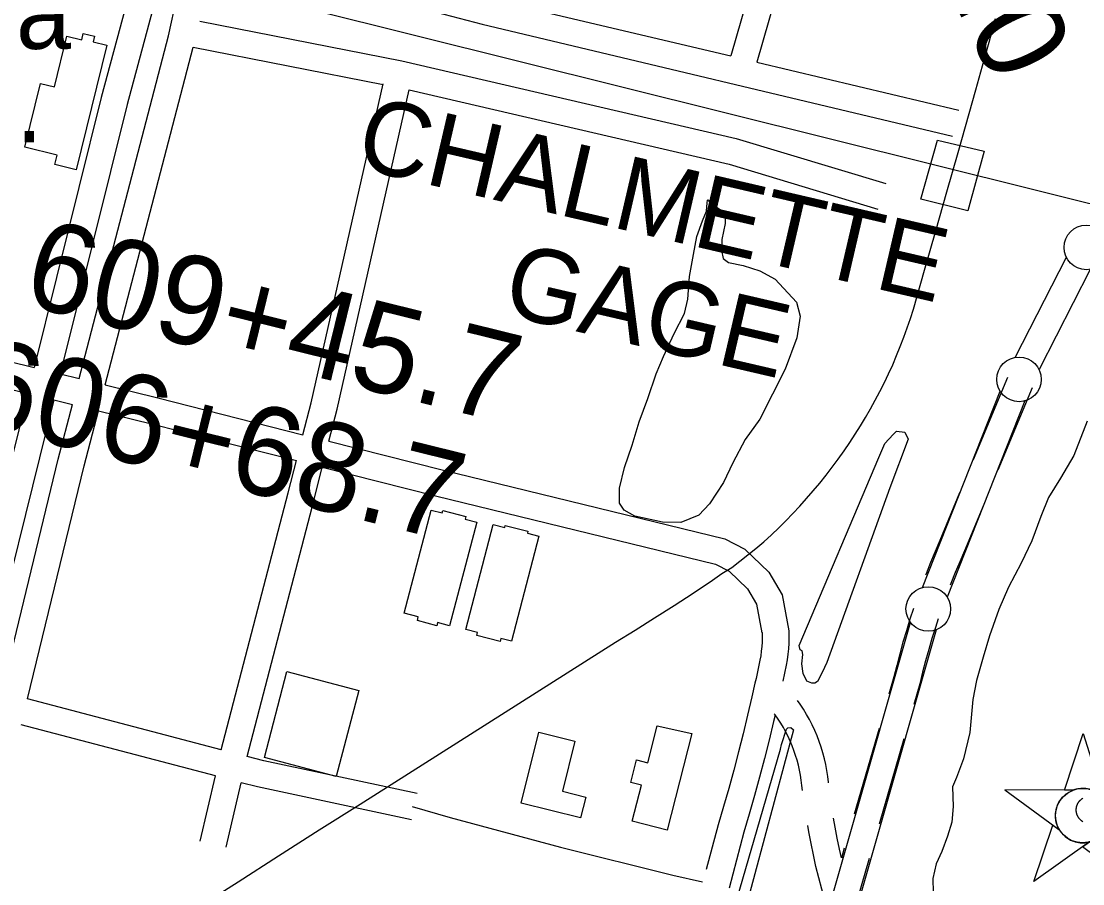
# Model space of a CAD drawing. Extents: x 3677843 to 3715951, y 511991 to 537744.
# Drawn here: x 3692882 to 3694073, y 534017 to 534986 of the extents above; entities that cross this region are included whole.
import ezdxf

# ---------------------------------------------------------------- set-up
doc = ezdxf.new("R2010")
doc.units = 0
for name, color, linetype in [('V-BLDG-IDEN', 7, 'Continuous'), ('V-BLDG-OTLN', 7, 'Continuous'), ('V-BRDG-OTLN', 7, 'Continuous'), ('V-CHAN-DOCK', 7, 'Continuous'), ('V-CHAN-NAID', 7, 'Continuous'), ('V-RAIL-TRAK', 7, 'Continuous'), ('V-RIVR-GAGE-IDEN', 7, 'Continuous'), ('V-ROAD-CNTR', 7, 'Continuous'), ('V-SITE-VEGE', 7, 'Continuous'), ('V-SURV-IDEN', 7, 'Continuous'), ('V-SURV-LINE', 7, 'Continuous'), ('V-TOPO-SHOR', 7, 'Continuous')]:
    doc.layers.add(name, color=color, linetype=linetype)

msp = doc.modelspace()

# ---------------------------------------------------------------- linework, layer by layer
at = {"layer": 'V-BLDG-OTLN'}
for points in [[(3692977.768, 534958.718), (3692943.644, 534818.9130000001), (3692919.6780000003, 534824.762), (3692922.24, 534835.256), (3692885.872, 534844.132), (3692903.348, 534915.714), (3692919.2630000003, 534911.831), (3692933.181, 534968.849), (3692949.806, 534964.79), (3692951.494, 534971.708), (3692963.977, 534968.659), (3692962.4590000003, 534962.453)], [(3693392.84, 534423.172), (3693362.3740000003, 534307.116), (3693349.009, 534310.6240000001), (3693348.0810000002, 534307.093), (3693326.278, 534312.816), (3693327.376, 534316.9940000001), (3693311.446, 534321.1730000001), (3693341.833, 534436.928), (3693354.252, 534433.6680000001), (3693355.022, 534436.599), (3693380.72, 534429.851), (3693379.862, 534426.58)], [(3693462.431, 534407.55), (3693431.9960000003, 534289.759), (3693419.9820000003, 534292.8640000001), (3693419.1380000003, 534289.591), (3693393.133, 534296.311), (3693393.934, 534299.416), (3693380.761, 534302.819), (3693411.186, 534420.571), (3693424.2630000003, 534417.194), (3693424.9220000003, 534419.742), (3693450.332, 534413.176), (3693449.725, 534410.833)], [(3693180.051, 534255.609), (3693260.711, 534234.387), (3693235.33, 534137.91), (3693154.67, 534159.134)], [(3693634.181, 534186.161), (3693606.481, 534077.66), (3693567.401, 534087.638), (3693577.754, 534128.1900000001), (3693565.775, 534131.246), (3693572.302, 534156.5650000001), (3693584.918, 534153.3420000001), (3693595.346, 534194.662)], [(3693503.1580000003, 534177.672), (3693489.051, 534121.393), (3693515.241, 534114.829), (3693509.345, 534091.312), (3693442.6410000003, 534108.032), (3693462.642, 534187.824)]]:
    msp.add_lwpolyline(points, close=True, dxfattribs=at)
at = {"layer": 'V-BRDG-OTLN'}
msp.add_lwpolyline([(3693891.272, 534786.02), (3693909.884, 534852.156), (3693962.311, 534839.649), (3693943.715, 534772.684)], close=True, dxfattribs=at)
at = {"layer": 'V-CHAN-DOCK'}
for points in [[(3694067.39, 534092.879), (3694067.2630000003, 534093.1140000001), (3694067.1380000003, 534093.354), (3694067.019, 534093.596), (3694066.904, 534093.839), (3694066.794, 534094.085), (3694066.687, 534094.333), (3694066.585, 534094.583), (3694066.487, 534094.835), (3694066.392, 534095.087), (3694066.304, 534095.343), (3694066.218, 534095.599), (3694066.139, 534095.855), (3694066.063, 534096.115), (3694065.9930000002, 534096.375), (3694065.926, 534096.635), (3694065.864, 534096.897), (3694065.807, 534097.161), (3694065.754, 534097.425), (3694065.704, 534097.692), (3694065.661, 534097.956), (3694065.622, 534098.224), (3694065.588, 534098.49), (3694065.559, 534098.759), (3694065.534, 534099.027), (3694065.514, 534099.297), (3694065.498, 534099.566), (3694065.487, 534099.834), (3694065.481, 534100.104), (3694065.4790000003, 534100.375), (3694065.483, 534100.643), (3694065.491, 534100.9130000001), (3694065.504, 534101.181), (3694065.522, 534101.452), (3694065.545, 534101.72), (3694065.571, 534101.988), (3694065.602, 534102.257), (3694065.639, 534102.523), (3694065.68, 534102.789), (3694065.725, 534103.055), (3694065.774, 534103.322), (3694065.829, 534103.584), (3694065.889, 534103.848), (3694065.952, 534104.11), (3694066.02, 534104.37), (3694066.093, 534104.63), (3694066.171, 534104.888), (3694066.253, 534105.144), (3694066.339, 534105.4), (3694066.431, 534105.654), (3694066.526, 534105.906), (3694066.626, 534106.156), (3694066.73, 534106.406), (3694066.839, 534106.652), (3694066.952, 534106.897), (3694067.068, 534107.1410000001), (3694067.1890000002, 534107.381), (3694067.3140000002, 534107.62), (3694067.443, 534107.856), (3694067.576, 534108.091), (3694067.715, 534108.323), (3694067.8570000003, 534108.552), (3694068.002, 534108.78), (3694068.1520000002, 534109.003), (3694068.305, 534109.224), (3694068.463, 534109.443), (3694068.625, 534109.66), (3694068.789, 534109.873), (3694068.957, 534110.084), (3694069.129, 534110.291), (3694069.305, 534110.496), (3694069.485, 534110.696), (3694069.667, 534110.895), (3694069.8540000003, 534111.09), (3694070.044, 534111.282), (3694070.237, 534111.469), (3694070.433, 534111.655), (3694070.632, 534111.835), (3694070.835, 534112.013), (3694071.039, 534112.187), (3694071.248, 534112.359), (3694071.461, 534112.525), (3694071.674, 534112.689), (3694071.893, 534112.849), (3694072.113, 534113.005), (3694072.336, 534113.156), (3694072.561, 534113.306), (3694072.788, 534113.449), (3694073.02, 534113.588)], [(3694072.924, 534087.106), (3694072.694, 534087.247), (3694072.469, 534087.394), (3694072.244, 534087.544), (3694072.022, 534087.697), (3694071.8030000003, 534087.853), (3694071.588, 534088.015), (3694071.373, 534088.181), (3694071.164, 534088.349), (3694070.955, 534088.5210000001), (3694070.753, 534088.697), (3694070.5500000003, 534088.875), (3694070.3510000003, 534089.059), (3694070.157, 534089.246), (3694069.966, 534089.434), (3694069.778, 534089.627), (3694069.594, 534089.823), (3694069.411, 534090.024), (3694069.233, 534090.227), (3694069.059, 534090.431), (3694068.889, 534090.64), (3694068.721, 534090.851), (3694068.557, 534091.066), (3694068.397, 534091.283), (3694068.242, 534091.503), (3694068.09, 534091.726), (3694067.943, 534091.951), (3694067.7970000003, 534092.18), (3694067.6580000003, 534092.41), (3694067.523, 534092.643), (3694067.39, 534092.879)]]:
    msp.add_lwpolyline(points, dxfattribs=at)
at = {"layer": 'V-CHAN-NAID'}
for points in [[(3694061.8310000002, 534122.49), (3694052.244, 534122.558), (3694073.37, 534186.042), (3694093.594, 534122.265), (3694084.007, 534122.333), (3694082.43, 534122.911), (3694080.335, 534123.531), (3694078.295, 534123.982), (3694076.259, 534124.29), (3694075.092, 534124.404), (3694073.558, 534124.485), (3694071.836, 534124.483), (3694070.466, 534124.4130000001), (3694068.56, 534124.212), (3694067.194, 534123.993), (3694065.41, 534123.609), (3694063.88, 534123.189), (3694062.848, 534122.858)], [(3694061.8310000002, 534122.49), (3693985.34, 534123.032), (3694046.9050000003, 534077.633), (3694045.792, 534079.542), (3694044.9820000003, 534081.17), (3694044.157, 534083.138), (3694043.461, 534085.192), (3694043.096, 534086.515), (3694042.735, 534088.1410000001), (3694042.491, 534089.586), (3694042.3030000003, 534091.184), (3694042.194, 534092.92), (3694042.182, 534094.501), (3694042.289, 534096.575), (3694042.472, 534098.193), (3694042.864, 534100.3960000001), (3694043.345, 534102.319), (3694043.948, 534104.206), (3694044.603, 534105.885), (3694045.33, 534107.473), (3694046.144, 534109.008), (3694047.205, 534110.745), (3694048.236, 534112.215), (3694049.236, 534113.484), (3694050.238, 534114.63), (3694051.5470000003, 534115.9670000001), (3694052.598, 534116.932), (3694054.315, 534118.329), (3694055.5270000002, 534119.199), (3694057.214, 534120.269), (3694058.9450000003, 534121.214), (3694060.3910000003, 534121.898)], [(3694080.265, 534064.362), (3694018.062, 534019.84), (3694039.188, 534083.323), (3694046.9050000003, 534077.633), (3694047.54, 534076.669), (3694048.923, 534074.81), (3694050.136, 534073.394), (3694051.602, 534071.8910000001), (3694052.991, 534070.64), (3694054.4450000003, 534069.484), (3694055.848, 534068.497), (3694057.526, 534067.461), (3694059.24, 534066.55), (3694061.031, 534065.7390000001), (3694062.477, 534065.183), (3694064.105, 534064.654), (3694066.3310000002, 534064.09), (3694067.863, 534063.803), (3694069.8880000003, 534063.546), (3694071.4250000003, 534063.442), (3694073.286, 534063.42), (3694074.975, 534063.498), (3694076.685, 534063.674), (3694078.5870000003, 534063.985)], [(3694098.296, 534077.268), (3694106.092, 534082.849), (3694126.316, 534019.072), (3694072.468, 534058.782), (3694080.265, 534064.362), (3694081.931, 534064.838), (3694083.543, 534065.398), (3694085.701, 534066.312), (3694087.436, 534067.196), (3694089.302, 534068.31), (3694091.041, 534069.522), (3694092.593, 534070.767), (3694093.88, 534071.935), (3694095.264, 534073.355), (3694096.468, 534074.757), (3694097.5870000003, 534076.229)]]:
    msp.add_lwpolyline(points, close=True, dxfattribs=at)
msp.add_circle((3694072.7166840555, 534093.9555819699), 30.540600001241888, dxfattribs=at)
at = {"layer": 'V-RAIL-TRAK'}
for points in [[(3693614.262, 534329.769), (3693635.913, 534343.831), (3693657.4420000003, 534358.083), (3693662.6520000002, 534361.978), (3693668.007, 534365.666), (3693673.502, 534369.144), (3693679.126, 534372.402), (3693688.24, 534379.415), (3693697.236, 534386.578), (3693706.108, 534393.892), (3693714.855, 534401.353), (3693723.473, 534408.955), (3693731.694, 534416.805), (3693739.761, 534424.813), (3693747.6720000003, 534432.974), (3693755.4220000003, 534441.287), (3693763.012, 534449.7490000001), (3693770.436, 534458.355), (3693777.69, 534467.102), (3693784.774, 534475.988), (3693791.686, 534485.007), (3693798.4220000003, 534494.162), (3693804.978, 534503.441), (3693811.353, 534512.846), (3693817.472, 534522.093), (3693823.4050000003, 534531.456), (3693829.1520000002, 534540.938), (3693834.71, 534550.531), (3693840.076, 534560.234), (3693845.2490000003, 534570.04), (3693850.2260000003, 534579.949), (3693855.004, 534589.953), (3693859.585, 534600.05), (3693863.9620000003, 534610.234), (3693868.1380000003, 534620.505), (3693872.109, 534630.856), (3693875.8710000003, 534641.284), (3693879.426, 534651.786), (3693882.775, 534662.356), (3693895.419, 534706.259), (3693907.986, 534750.186), (3693920.47, 534794.1410000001), (3693932.873, 534838.1190000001), (3693945.194, 534882.1190000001), (3693952.878, 534908.7220000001), (3693960.37, 534935.379), (3693967.667, 534962.089), (3693974.767, 534988.848)], [(3693041.389, 533966.626), (3693125.128, 534019.687), (3693170.622, 534048.968), (3693216.272, 534078.008), (3693262.073, 534106.807), (3693548.5700000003, 534288.735), (3693570.588, 534302.219), (3693592.485, 534315.898), (3693614.262, 534329.769)]]:
    msp.add_lwpolyline(points, dxfattribs=at)
at = {"layer": 'V-ROAD-CNTR'}
for p, q in [((3693988.233744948, 534585.712686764), (3693949.9825015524, 534493.3176571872)), ((3694015.952255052, 534574.237313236), (3693977.7010116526, 534481.8422836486)), ((3693844.2422862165, 534191.8092449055), (3693816.3957029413, 534095.7647972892)), ((3693872.134127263, 534180.2768156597), (3693844.2875437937, 534084.2323673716))]:
    msp.add_line(p, q, dxfattribs=at)
for points in [[(3693888.398184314, 535557.2138593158), (3693851.7112576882, 535421.3931309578), (3693755.5274500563, 535107.5157587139), (3693707.278546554, 534939.64309446)], [(3693091.418778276, 535347.8132781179), (3693082.144796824, 535310.5753525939), (3692971.6500178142, 534899.8351740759), (3692896.50216811, 534596.9547798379)], [(3693120.47672016, 535340.3502930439), (3693111.1887387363, 535303.0533676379), (3693000.695959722, 534892.325189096), (3692925.63210985, 534589.781794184)], [(3692947.0230670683, 534584.511804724), (3693047.139866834, 534969.081035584), (3693084.618791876, 535140.353693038), (3693134.8066915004, 535336.6683004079)], [(3693748.192464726, 535185.9716018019), (3693726.767507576, 535116.053741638), (3693678.062604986, 534946.5940805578)], [(3693098.04176503, 535061.3578510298), (3693398.9661631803, 534982.1570094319), (3693926.77510756, 534856.5832605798)], [(3693352.7782555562, 535025.334923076), (3693406.2561486, 535011.2589512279), (3693678.0616049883, 534946.59308056)], [(3695886.3971883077, 534330.6213125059), (3693205.8875493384, 534998.7889761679)], [(3693082.418796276, 534985.522002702), (3693308.933343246, 534941.1360914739), (3693683.9245932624, 534854.0932655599), (3693851.731257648, 534803.335367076)], [(3692976.1550088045, 534577.3388190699), (3693074.84681142, 534956.435060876)], [(3693074.84681142, 534956.435060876), (3693287.763385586, 534914.7141443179)], [(3693707.278546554, 534939.642094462), (3693933.719093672, 534885.7692022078)], [(3693197.965565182, 534521.5549306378), (3693207.0495470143, 534557.18885937), (3693287.879385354, 534915.2261432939)], [(3693227.04650702, 534514.1859453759), (3693236.2214886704, 534550.17887339), (3693317.102326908, 534908.4411568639)], [(3693317.102326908, 534908.442156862), (3693676.182608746, 534825.09332356), (3693843.0452750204, 534774.6194245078)], [(3692611.9757371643, 534667.196639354), (3692655.22765066, 534656.3716610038), (3692896.50216811, 534596.9547798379)], [(3692604.376752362, 534638.1736973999), (3692647.9996651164, 534627.2557192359), (3692889.27718256, 534567.8378380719)], [(3692925.631109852, 534589.7807941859), (3692947.0230670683, 534584.5128047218)], [(3692976.1550088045, 534577.3388190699), (3693035.2688905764, 534562.7818481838), (3693197.965565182, 534521.5549306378)], [(3692889.2781825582, 534567.8378380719), (3692809.38734234, 534245.8434820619)], [(3692918.4071243, 534560.664852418), (3692838.405284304, 534238.2184973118)], [(3692918.4071243, 534560.6638524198), (3692939.4640821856, 534555.4788627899)], [(3692859.9542412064, 534232.5555086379), (3692923.439114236, 534493.9199859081), (3692939.465082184, 534555.477862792)], [(3692888.974183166, 534224.9305238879), (3692952.5330560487, 534486.600000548), (3692968.59702392, 534548.3038771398)], [(3692968.596023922, 534548.3048771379), (3693027.99690512, 534533.6759063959), (3693190.554580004, 534492.4849887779)], [(3693227.04650702, 534514.1859453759), (3693354.0132530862, 534482.0140097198), (3693671.2266186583, 534404.6051645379), (3693693.639573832, 534393.2181873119), (3693720.458520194, 534367.2842391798), (3693735.454490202, 534341.86429002), (3693743.0553083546, 534301.3655521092)], [(3693106.3217484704, 534167.8216381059), (3693181.302598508, 534456.185061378), (3693190.555580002, 534492.4839887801)], [(3693135.337690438, 534160.198653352), (3693210.3545404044, 534448.7050763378), (3693219.63652184, 534485.116003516)], [(3693219.635521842, 534485.116003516), (3693346.7732675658, 534452.9000679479), (3693660.736639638, 534376.2852211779), (3693676.0296090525, 534368.5162367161), (3693696.6845677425, 534348.542276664), (3693706.9405472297, 534331.156311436), (3693712.937755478, 534299.2055032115)], [(3693934.6820041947, 534456.3596453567), (3693912.5103739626, 534402.8045645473), (3693907.209831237, 534390.6028251), (3693902.007869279, 534378.0904377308), (3693897.001236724, 534365.5031469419), (3693896.420222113, 534363.9740059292)], [(3693962.400514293, 534444.8842718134), (3693940.1296260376, 534391.0894354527), (3693934.8201687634, 534378.8671749), (3693929.7981307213, 534366.7875622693), (3693924.962763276, 534354.6308530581), (3693924.1508102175, 534352.4939176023)], [(3693882.8493703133, 534326.3507481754), (3693878.9422516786, 534314.416259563), (3693874.9273395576, 534301.4761550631), (3693871.114102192, 534288.4787945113), (3693867.501094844, 534275.4217054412), (3693864.0914391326, 534262.3081146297), (3693860.99081948, 534249.5758875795), (3693855.3809195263, 534230.2270239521)], [(3693910.6497831, 534314.8462603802), (3693907.525748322, 534305.303740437), (3693903.6486604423, 534292.8078449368), (3693899.9658978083, 534280.2552054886), (3693896.476905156, 534267.6462945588), (3693893.1845608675, 534254.9838853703), (3693889.98518052, 534241.8461124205), (3693883.2727606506, 534218.694594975)], [(3693713.077997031, 534299.6407700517), (3693713.100457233, 534299.1224506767), (3693713.139382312, 534293.9770984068), (3693712.9926668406, 534288.832094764), (3693712.6638971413, 534283.6958606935), (3693712.1502288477, 534278.5736728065), (3693711.4564251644, 534273.4724948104), (3693710.581641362, 534268.4178874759), (3693706.230195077, 534247.8849612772), (3693705.0563610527, 534242.6027081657), (3693701.6311213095, 534227.1965949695), (3693696.832807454, 534206.550238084), (3693691.835054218, 534185.9513902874), (3693686.6377084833, 534165.4013653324), (3693681.2416199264, 534144.9035785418), (3693675.648043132, 534124.4580224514), (3693669.8549259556, 534104.0683952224), (3693663.7878110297, 534083.4748104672), (3693650.454574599, 534033.3111428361)], [(3693743.0498707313, 534300.9395336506), (3693743.095542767, 534299.8855493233), (3693743.142617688, 534293.6629015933), (3693742.9653331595, 534287.4459052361), (3693742.5681028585, 534281.2401393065), (3693741.9477711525, 534275.0543271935), (3693741.1095748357, 534268.8915051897), (3693740.046358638, 534262.748112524), (3693736.237474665, 534244.7753447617)], [(3693106.3217484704, 534167.8216381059), (3692888.974183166, 534224.9305238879)], [(3693787.560656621, 534130.7203782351), (3693787.455231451, 534131.5649597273), (3693786.6915453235, 534137.9480079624), (3693785.6585499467, 534144.5968995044), (3693784.3980393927, 534151.2029285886), (3693782.9061326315, 534157.766884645), (3693781.1883271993, 534164.2696181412), (3693779.2456449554, 534170.7134257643), (3693777.0773161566, 534177.0882473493), (3693774.688868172, 534183.377971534), (3693772.0866097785, 534189.5824402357), (3693769.267887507, 534195.6970828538), (3693766.237026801, 534201.7067723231), (3693763.003304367, 534207.6052814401), (3693759.5635867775, 534213.3912462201), (3693755.9268815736, 534219.0549674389), (3693752.958109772, 534223.3402081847)], [(3693727.6587346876, 534206.6638369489), (3693726.0211925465, 534199.6177619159), (3693720.954945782, 534178.7366097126), (3693715.6862915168, 534157.9046346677), (3693710.2163800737, 534137.1264214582), (3693704.545956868, 534116.3999775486), (3693698.6730740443, 534095.7296047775), (3693692.678188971, 534075.3811895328), (3693675.9570638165, 534012.4712599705)], [(3693758.3866970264, 534122.2376654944), (3693757.6767685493, 534127.9250402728), (3693756.966454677, 534133.8619920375), (3693756.093450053, 534139.4811004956), (3693755.027960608, 534145.0650714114), (3693753.7678673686, 534150.6091153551), (3693752.3156728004, 534156.1063818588), (3693750.674355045, 534161.5505742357), (3693748.8446838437, 534166.9297526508), (3693746.8251318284, 534172.248028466), (3693744.6233902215, 534177.4975597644), (3693742.244112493, 534182.6589171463), (3693739.6829731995, 534187.7372276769), (3693736.948695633, 534192.72471856), (3693734.0404132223, 534197.6167537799), (3693730.967118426, 534202.4030325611), (3693727.729256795, 534207.0766880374), (3693726.777516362, 534208.3533692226)], [(3693099.7277616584, 534138.5376966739), (3692881.89219733, 534195.7735822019)], [(3693325.972309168, 534118.765736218), (3693153.939653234, 534155.3106631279), (3693135.337690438, 534160.198653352)], [(3693082.738795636, 534065.4228429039), (3693099.7277616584, 534138.5376966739)], [(3693111.960737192, 534058.6328564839), (3693128.7547036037, 534130.911711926)], [(3693319.7383216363, 534089.41979491), (3693147.007667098, 534126.11472152), (3693128.7547036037, 534130.911711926)], [(3693320.5568149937, 534104.1837867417), (3693363.171, 534091.851), (3693486.776, 534058.7490000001), (3693612.8850000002, 534027.267), (3693646.03245465, 534019.8205409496)], [(3693802.1229587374, 534046.5372917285), (3693799.956132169, 534056.1890327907), (3693797.37234048, 534068.6310741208), (3693794.988702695, 534081.1213753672), (3693793.21677258, 534091.2918560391)], [(3693785.8680309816, 533990.404524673), (3693783.4178180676, 533998.741979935), (3693779.9146346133, 534011.4300661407), (3693776.616087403, 534024.1790835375), (3693773.5201040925, 534036.9878358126), (3693770.631867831, 534049.8529672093), (3693767.9496595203, 534062.7689258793), (3693765.4752973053, 534075.7346246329), (3693764.23861518, 534082.8329021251)], [(3693805.2570696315, 534057.3470182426), (3693801.9806845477, 534046.0465799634)], [(3693833.1489104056, 534045.8145880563), (3693815.899807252, 533986.3214513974), (3693805.461993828, 533949.7242443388)]]:
    msp.add_lwpolyline(points, dxfattribs=at)
at = {"layer": 'V-SITE-VEGE'}
for points in [[(3693654.024, 534782.528), (3693671.395, 534770.376), (3693671.585, 534758.534), (3693667.733, 534740.706), (3693667.342, 534728.263), (3693669.2630000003, 534719.411), (3693675.261, 534714.772), (3693691.893, 534711.49), (3693710.356, 534705.276), (3693727.6780000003, 534696.082), (3693751.787, 534670.419), (3693755.598, 534654.492), (3693751.85, 534630.149), (3693738.801, 534594.997), (3693710.7, 534538.872), (3693693.896, 534516.094), (3693680.111, 534489.812), (3693669.812, 534467.732), (3693654.2120000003, 534443.787), (3693641.981, 534431.153), (3693621.9760000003, 534423.129), (3693601.247, 534423.383), (3693570.342, 534429.986), (3693558.386, 534436.898), (3693552.932, 534444.508), (3693553.2460000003, 534461.687), (3693558.79, 534484.872), (3693567.264, 534509.884), (3693575.128, 534536.0700000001), (3693584.768, 534562.285), (3693594.39, 534589.683), (3693602.361, 534609.356), (3693614.378, 534635.015), (3693625.853, 534657.707), (3693629.736, 534673.759), (3693631.69, 534699.257), (3693636.032, 534723.608), (3693639.847, 534743.805), (3693646.294, 534761.42), (3693650.505, 534772.473), (3693651.578, 534781.785), (3693651.642, 534784.921), (3693652.123, 534785.0210000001), (3693652.842, 534784.759), (3693653.419, 534783.112)], [(3693755.7460000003, 534280.201), (3693754.484, 534284.9180000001), (3693844.014, 534496.003), (3693850.869, 534511.511), (3693860.1750000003, 534521.728), (3693863.669, 534525.339), (3693873.162, 534524.308), (3693876.84, 534516.669), (3693856.413, 534461.859), (3693785.5870000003, 534265.884), (3693780.443, 534254.55), (3693775.2800000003, 534244.398), (3693772.349, 534242.573), (3693768.796, 534242.5160000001), (3693763.43, 534244.797), (3693759.1410000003, 534253.61), (3693757.7830000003, 534264.245), (3693758.793, 534274.921), (3693758.134, 534279.056)], [(3693734.977, 534173.867), (3693740.617, 534191.132), (3693741.782, 534192.334), (3693745.323, 534192.983), (3693748.3340000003, 534190.073), (3693672.4020000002, 533907.557), (3693586.89, 533595.278), (3693487.0810000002, 533251.974), (3693491.943, 533244.356), (3693539.8540000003, 533211.383), (3693541.066, 533209.626), (3693539.927, 533206.648), (3693538.774, 533204.852), (3693536.4250000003, 533203.629), (3693520.394, 533206.328), (3693476.403, 533216.863), (3693470.453, 533218.5430000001), (3693464.4960000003, 533220.814), (3693458.401, 533231.375), (3693527.021, 533490.083), (3693629.575, 533810.337), (3693733.879, 534168.52)]]:
    msp.add_lwpolyline(points, close=True, dxfattribs=at)
at = {"layer": 'V-SURV-LINE'}
for points in [[(3693997.017653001, 534608.224844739), (3694054.383422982, 534720.705897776)], [(3694081.100715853, 534707.0608784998), (3694023.7351738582, 534594.58027249)], [(3693892.8874524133, 534350.0511870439), (3693980.004470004, 534570.5315876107)], [(3694007.898628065, 534559.4900166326), (3693920.781955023, 534339.0104880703)], [(3693673.547196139, 533588.6376398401), (3693879.5878467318, 534310.8561657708)], [(3693908.433729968, 534302.615101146), (3693702.3932164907, 533580.397055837)]]:
    msp.add_lwpolyline(points, dxfattribs=at)
for centre in [(3694076.82345, 534731.68949), (3694001.29535, 534583.59629), (3693899.491480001, 534325.9451500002)]:
    msp.add_circle(centre, 25, dxfattribs=at)
at = {"layer": 'V-TOPO-SHOR'}
msp.add_lwpolyline([(3694077.769, 534536.689), (3694062.636, 534498.02), (3694047.9420000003, 534472.822), (3694034.505, 534450.929), (3694025.656, 534429.767), (3694015.594, 534402.346), (3694003.853, 534377.197), (3693989.5130000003, 534350.362), (3693978.757, 534325.229), (3693968.068, 534295.825), (3693961.238, 534271.741), (3693953.779, 534245.676), (3693949.532, 534224.26), (3693946.191, 534187.427), (3693939.122, 534157.753), (3693931.255, 534136.61), (3693926.825, 534126.355), (3693927.518, 534104.036), (3693925.83, 534086.604), (3693921.163, 534070.765), (3693914.875, 534053.586), (3693908.529, 534040.018), (3693904.529, 534023.532), (3693905.112, 534007.778)], dxfattribs=at)

# ---------------------------------------------------------------- texts
at = {"layer": 'V-BLDG-IDEN'}
for s, p in [('St. Cecilia', (3692438.110084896, 534954.6150645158)), ('Sch.', (3692684.19759272, 534849.5642746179))]:
    msp.add_text(s, height=82.99983200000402, dxfattribs=at).set_placement(p)
at = {"layer": 'V-RIVR-GAGE-IDEN'}
for s, p in [('CHALMETTE', (3693254.4027839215, 534821.85342382)), ('GAGE', (3693419.425088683, 534657.2022962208))]:
    msp.add_text(s, height=83, rotation=346.9104965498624, dxfattribs=at).set_placement(p)
at = {"layer": 'V-SURV-IDEN'}
for s, height, rotation, p in [('   611+12.0  ', 100, 295.97371795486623, (3693679.878802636, 535516.9388498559)), ('   609+45.7  ', 100.00000000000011, 346.11681991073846, (3692772.951252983, 534695.055188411)), ('   606+68.7  ', 100, 346.1373881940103, (3692709.7541976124, 534562.3261325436))]:
    msp.add_text(s, height=height, rotation=rotation, dxfattribs=at).set_placement(p)

doc.saveas('drawing.dxf')
